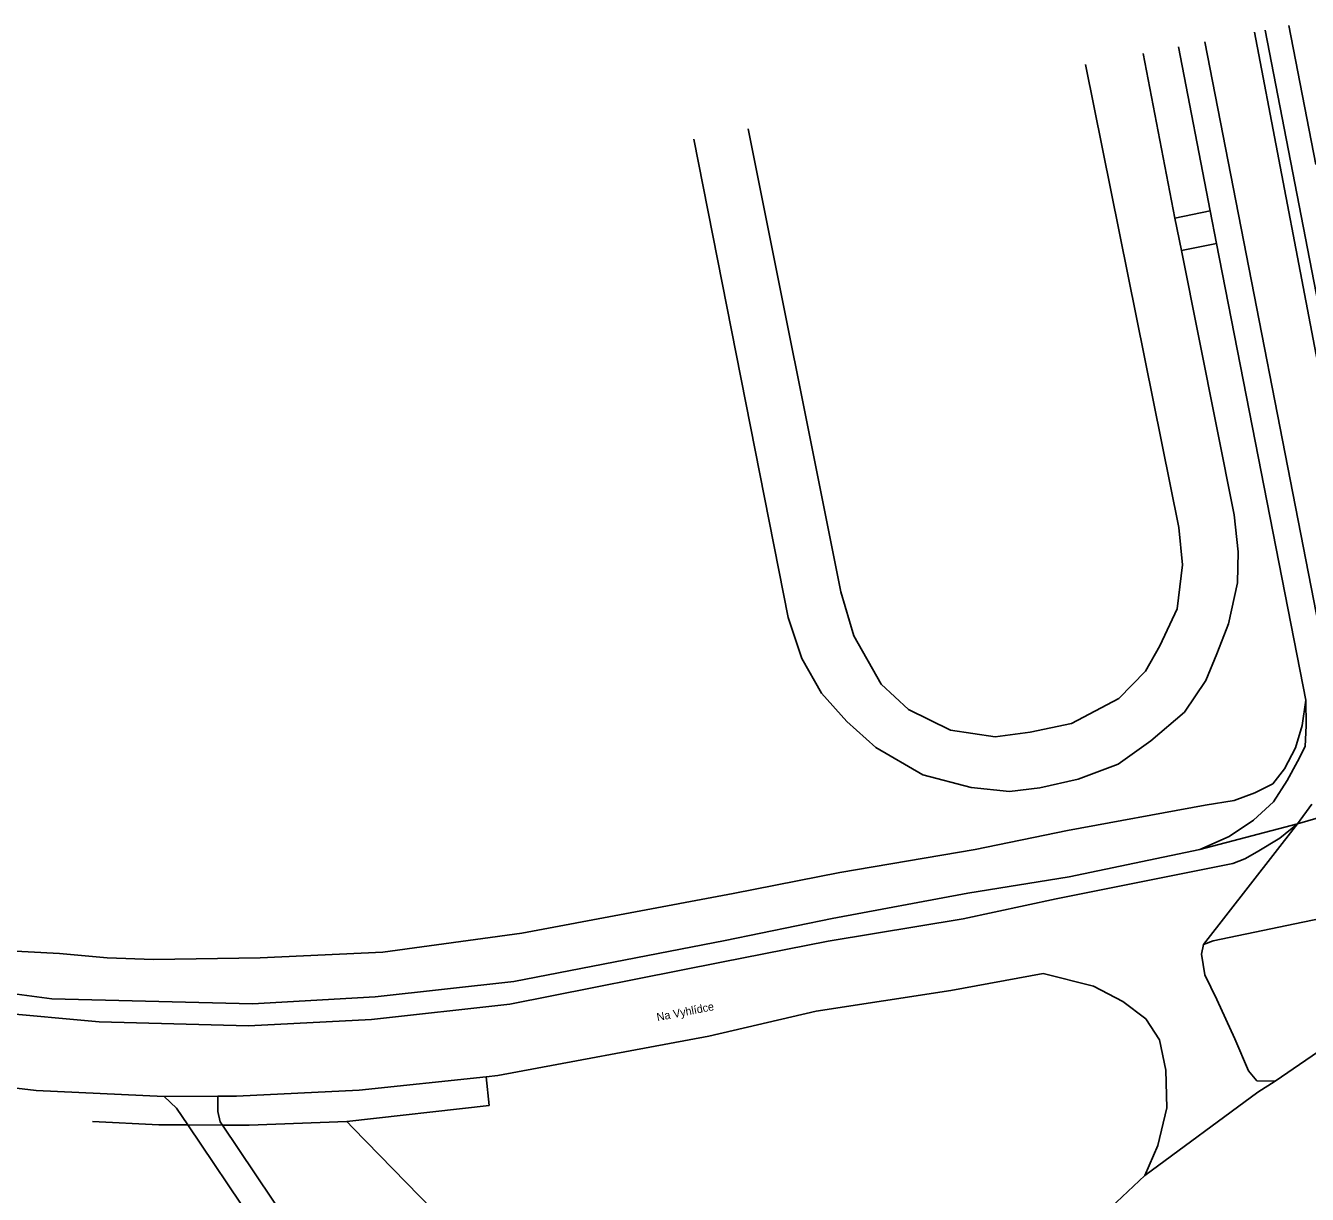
# Model space of a CAD drawing. Extents: x -452714 to -451134, y -1100194 to -1099694.
# Drawn here: x -452627.8 to -452516.4, y -1100019.1 to -1099917.5 of the extents above; entities that cross this region are included whole.
import ezdxf

# ---------------------------------------------------------------- set-up
doc = ezdxf.new("R2010")
doc.units = 0
doc.layers.add('Polohopis', color=7, linetype='Continuous')

msp = doc.modelspace()

# ---------------------------------------------------------------- linework, layer by layer
at = {"layer": 'Polohopis'}
for p, q in [((-452514.6, -1099951.28), (-452520.94, -1099918.08)), ((-452514.6, -1099951.28), (-452520.94, -1099918.08)), ((-452520.03, -1099917.9), (-452513.93, -1099949.28)), ((-452520.03, -1099917.9), (-452513.93, -1099949.28)), ((-452515.62, -1099929.58), (-452517.98, -1099917.51)), ((-452515.62, -1099929.58), (-452517.98, -1099917.51)), ((-452527.57, -1099919.35), (-452524.8, -1099933.61)), ((-452527.57, -1099919.35), (-452524.8, -1099933.61)), ((-452514.22, -1099975.53), (-452525.28, -1099918.91)), ((-452514.22, -1099975.53), (-452525.28, -1099918.91)), ((-452530.64, -1099919.93), (-452527.86, -1099934.24)), ((-452530.64, -1099919.93), (-452527.86, -1099934.24)), ((-452535.64, -1099920.89), (-452527.52, -1099961.12)), ((-452535.64, -1099920.89), (-452527.52, -1099961.12)), ((-452556.91, -1099966.72), (-452564.95, -1099926.49)), ((-452556.91, -1099966.72), (-452564.95, -1099926.49)), ((-452561.48, -1099968.96), (-452569.67, -1099927.39)), ((-452561.48, -1099968.96), (-452569.67, -1099927.39)), ((-452527.86, -1099934.24), (-452524.8, -1099933.61)), ((-452527.86, -1099934.24), (-452524.8, -1099933.61)), ((-452524.8, -1099933.61), (-452524.25, -1099936.46)), ((-452524.8, -1099933.61), (-452524.25, -1099936.46)), ((-452527.86, -1099934.24), (-452527.29, -1099937.07)), ((-452527.86, -1099934.24), (-452527.29, -1099937.07)), ((-452527.29, -1099937.07), (-452524.25, -1099936.46)), ((-452527.29, -1099937.07), (-452524.25, -1099936.46)), ((-452527.29, -1099937.07), (-452522.72, -1099960.03)), ((-452527.29, -1099937.07), (-452522.72, -1099960.03)), ((-452524.25, -1099936.46), (-452516.48, -1099976.13)), ((-452524.25, -1099936.46), (-452516.48, -1099976.13)), ((-452522.72, -1099960.03), (-452522.36, -1099963.26)), ((-452522.72, -1099960.03), (-452522.36, -1099963.26)), ((-452527.52, -1099961.12), (-452527.22, -1099964.38)), ((-452527.52, -1099961.12), (-452527.22, -1099964.38)), ((-452522.36, -1099963.26), (-452522.43, -1099965.95)), ((-452522.36, -1099963.26), (-452522.43, -1099965.95)), ((-452527.22, -1099964.38), (-452527.68, -1099968.19)), ((-452527.22, -1099964.38), (-452527.68, -1099968.19)), ((-452522.43, -1099965.95), (-452523.22, -1099969.5)), ((-452522.43, -1099965.95), (-452523.22, -1099969.5)), ((-452555.77, -1099970.55), (-452556.91, -1099966.72)), ((-452555.77, -1099970.55), (-452556.91, -1099966.72)), ((-452527.68, -1099968.19), (-452529.17, -1099971.41)), ((-452527.68, -1099968.19), (-452529.17, -1099971.41)), ((-452560.29, -1099972.52), (-452561.48, -1099968.96)), ((-452560.29, -1099972.52), (-452561.48, -1099968.96)), ((-452523.22, -1099969.5), (-452524.23, -1099972.12)), ((-452523.22, -1099969.5), (-452524.23, -1099972.12)), ((-452553.4, -1099974.75), (-452555.77, -1099970.55)), ((-452553.4, -1099974.75), (-452555.77, -1099970.55)), ((-452529.17, -1099971.41), (-452530.43, -1099973.63)), ((-452529.17, -1099971.41), (-452530.43, -1099973.63)), ((-452558.59, -1099975.54), (-452560.29, -1099972.52)), ((-452558.59, -1099975.54), (-452560.29, -1099972.52)), ((-452524.23, -1099972.12), (-452525.18, -1099974.42)), ((-452524.23, -1099972.12), (-452525.18, -1099974.42)), ((-452530.43, -1099973.63), (-452532.73, -1099976)), ((-452530.43, -1099973.63), (-452532.73, -1099976)), ((-452551.03, -1099976.96), (-452553.4, -1099974.75)), ((-452551.03, -1099976.96), (-452553.4, -1099974.75)), ((-452525.18, -1099974.42), (-452527.02, -1099977.18)), ((-452525.18, -1099974.42), (-452527.02, -1099977.18)), ((-452556.39, -1099977.98), (-452558.59, -1099975.54)), ((-452556.39, -1099977.98), (-452558.59, -1099975.54)), ((-452532.73, -1099976), (-452536.87, -1099978.16)), ((-452532.73, -1099976), (-452536.87, -1099978.16)), ((-452516.48, -1099976.13), (-452516.8, -1099978.34)), ((-452516.48, -1099976.13), (-452516.8, -1099978.34)), ((-452516.48, -1099976.13), (-452516.46, -1099978.34)), ((-452516.48, -1099976.13), (-452516.46, -1099978.34)), ((-452547.37, -1099978.75), (-452551.03, -1099976.96)), ((-452547.37, -1099978.75), (-452551.03, -1099976.96)), ((-452527.02, -1099977.18), (-452529.97, -1099979.67)), ((-452527.02, -1099977.18), (-452529.97, -1099979.67)), ((-452553.86, -1099980.26), (-452556.39, -1099977.98)), ((-452553.86, -1099980.26), (-452556.39, -1099977.98)), ((-452536.87, -1099978.16), (-452540.45, -1099978.92)), ((-452536.87, -1099978.16), (-452540.45, -1099978.92)), ((-452516.8, -1099978.34), (-452517.4, -1099980.27)), ((-452516.8, -1099978.34), (-452517.4, -1099980.27)), ((-452516.46, -1099978.34), (-452516.54, -1099980.16)), ((-452516.46, -1099978.34), (-452516.54, -1099980.16)), ((-452543.49, -1099979.34), (-452547.37, -1099978.75)), ((-452543.49, -1099979.34), (-452547.37, -1099978.75)), ((-452540.45, -1099978.92), (-452543.49, -1099979.34)), ((-452540.45, -1099978.92), (-452543.49, -1099979.34)), ((-452549.79, -1099982.62), (-452553.86, -1099980.26)), ((-452549.79, -1099982.62), (-452553.86, -1099980.26)), ((-452529.97, -1099979.67), (-452532.8, -1099981.7)), ((-452529.97, -1099979.67), (-452532.8, -1099981.7)), ((-452517.4, -1099980.27), (-452518.34, -1099982.11)), ((-452517.4, -1099980.27), (-452518.34, -1099982.11)), ((-452516.54, -1099980.16), (-452517.2, -1099981.47)), ((-452516.54, -1099980.16), (-452517.2, -1099981.47)), ((-452532.8, -1099981.7), (-452536.27, -1099983.02)), ((-452532.8, -1099981.7), (-452536.27, -1099983.02)), ((-452517.2, -1099981.47), (-452518.1, -1099983.11)), ((-452517.2, -1099981.47), (-452518.1, -1099983.11)), ((-452545.59, -1099983.74), (-452549.79, -1099982.62)), ((-452545.59, -1099983.74), (-452549.79, -1099982.62)), ((-452518.34, -1099982.11), (-452519.36, -1099983.42)), ((-452518.34, -1099982.11), (-452519.36, -1099983.42)), ((-452542.25, -1099984.07), (-452545.59, -1099983.74)), ((-452542.25, -1099984.07), (-452545.59, -1099983.74)), ((-452539.62, -1099983.75), (-452542.25, -1099984.07)), ((-452539.62, -1099983.75), (-452542.25, -1099984.07)), ((-452536.27, -1099983.02), (-452539.62, -1099983.75)), ((-452536.27, -1099983.02), (-452539.62, -1099983.75)), ((-452519.36, -1099983.42), (-452520.93, -1099984.2)), ((-452519.36, -1099983.42), (-452520.93, -1099984.2)), ((-452518.1, -1099983.11), (-452519.29, -1099984.99)), ((-452518.1, -1099983.11), (-452519.29, -1099984.99)), ((-452505.84, -1099983.57), (-452517.2, -1099986.88)), ((-452505.84, -1099983.57), (-452517.2, -1099986.88)), ((-452522.72, -1099984.85), (-452525.24, -1099985.26)), ((-452522.72, -1099984.85), (-452525.24, -1099985.26)), ((-452520.93, -1099984.2), (-452522.72, -1099984.85)), ((-452520.93, -1099984.2), (-452522.72, -1099984.85)), ((-452519.29, -1099984.99), (-452521.03, -1099986.58)), ((-452519.29, -1099984.99), (-452521.03, -1099986.58)), ((-452537.19, -1099987.48), (-452525.24, -1099985.26)), ((-452537.19, -1099987.48), (-452525.24, -1099985.26)), ((-452517.2, -1099986.88), (-452515.96, -1099985.19)), ((-452517.2, -1099986.88), (-452515.96, -1099985.19)), ((-452525.7, -1099989.12), (-452517.2, -1099986.88)), ((-452525.7, -1099989.12), (-452517.2, -1099986.88)), ((-452525.38, -1099997.38), (-452517.2, -1099986.88)), ((-452525.38, -1099997.38), (-452517.2, -1099986.88)), ((-452521.03, -1099986.58), (-452523.16, -1099987.98)), ((-452521.03, -1099986.58), (-452523.16, -1099987.98)), ((-452518.74, -1099988.12), (-452517.2, -1099986.88)), ((-452518.74, -1099988.12), (-452517.2, -1099986.88)), ((-452545.23, -1099989.12), (-452537.19, -1099987.48)), ((-452545.23, -1099989.12), (-452537.19, -1099987.48)), ((-452525.7, -1099989.12), (-452523.16, -1099987.98)), ((-452525.7, -1099989.12), (-452523.16, -1099987.98)), ((-452520.73, -1099989.32), (-452518.74, -1099988.12)), ((-452520.73, -1099989.32), (-452518.74, -1099988.12)), ((-452556.98, -1099991.13), (-452545.23, -1099989.12)), ((-452556.98, -1099991.13), (-452545.23, -1099989.12)), ((-452537.06, -1099991.49), (-452525.7, -1099989.12)), ((-452537.06, -1099991.49), (-452525.7, -1099989.12)), ((-452521.79, -1099989.92), (-452520.73, -1099989.32)), ((-452521.79, -1099989.92), (-452520.73, -1099989.32)), ((-452538.2, -1099993.4), (-452522.84, -1099990.35)), ((-452538.2, -1099993.4), (-452522.84, -1099990.35)), ((-452522.84, -1099990.35), (-452521.79, -1099989.92)), ((-452522.84, -1099990.35), (-452521.79, -1099989.92)), ((-452566.26, -1099992.94), (-452556.98, -1099991.13)), ((-452566.26, -1099992.94), (-452556.98, -1099991.13)), ((-452545.88, -1099992.92), (-452537.06, -1099991.49)), ((-452545.88, -1099992.92), (-452537.06, -1099991.49)), ((-452584.62, -1099996.39), (-452566.26, -1099992.94)), ((-452584.62, -1099996.39), (-452566.26, -1099992.94)), ((-452557.66, -1099995.12), (-452545.88, -1099992.92)), ((-452557.66, -1099995.12), (-452545.88, -1099992.92)), ((-452538.2, -1099993.4), (-452546.26, -1099995.14)), ((-452538.2, -1099993.4), (-452546.26, -1099995.14)), ((-452524.53, -1099997.05), (-452506.96, -1099993.4)), ((-452524.53, -1099997.05), (-452506.96, -1099993.4)), ((-452566.96, -1099997.03), (-452557.66, -1099995.12)), ((-452566.96, -1099997.03), (-452557.66, -1099995.12)), ((-452546.26, -1099995.14), (-452558, -1099997.08)), ((-452546.26, -1099995.14), (-452558, -1099997.08)), ((-452596.71, -1099998.03), (-452584.62, -1099996.39)), ((-452596.71, -1099998.03), (-452584.62, -1099996.39)), ((-452585.33, -1100000.58), (-452566.96, -1099997.03)), ((-452585.33, -1100000.58), (-452566.96, -1099997.03)), ((-452558, -1099997.08), (-452567.28, -1099998.91)), ((-452558, -1099997.08), (-452567.28, -1099998.91)), ((-452525.38, -1099997.38), (-452524.53, -1099997.05)), ((-452525.38, -1099997.38), (-452524.53, -1099997.05)), ((-452631.13, -1099997.83), (-452624.81, -1099998.16)), ((-452631.13, -1099997.83), (-452624.81, -1099998.16)), ((-452624.81, -1099998.16), (-452620.66, -1099998.53)), ((-452624.81, -1099998.16), (-452620.66, -1099998.53)), ((-452607.37, -1099998.54), (-452596.71, -1099998.03)), ((-452607.37, -1099998.54), (-452596.71, -1099998.03)), ((-452525.56, -1099998.21), (-452525.38, -1099997.38)), ((-452525.56, -1099998.21), (-452525.38, -1099997.38)), ((-452525.27, -1100000.01), (-452525.56, -1099998.21)), ((-452525.27, -1100000.01), (-452525.56, -1099998.21)), ((-452620.66, -1099998.53), (-452616.66, -1099998.68)), ((-452620.66, -1099998.53), (-452616.66, -1099998.68)), ((-452616.66, -1099998.68), (-452607.37, -1099998.54)), ((-452616.66, -1099998.68), (-452607.37, -1099998.54)), ((-452567.28, -1099998.91), (-452585.67, -1100002.57)), ((-452567.28, -1099998.91), (-452585.67, -1100002.57)), ((-452504.73, -1099999.32), (-452519.14, -1100009.24)), ((-452504.73, -1099999.32), (-452519.14, -1100009.24)), ((-452597.37, -1100001.92), (-452585.33, -1100000.58)), ((-452597.37, -1100001.92), (-452585.33, -1100000.58)), ((-452547.33, -1100001.38), (-452539.31, -1099999.9)), ((-452547.33, -1100001.38), (-452539.31, -1099999.9)), ((-452539.31, -1099999.9), (-452534.93, -1100001.01)), ((-452539.31, -1099999.9), (-452534.93, -1100001.01)), ((-452524.23, -1100002.15), (-452525.27, -1100000.01)), ((-452524.23, -1100002.15), (-452525.27, -1100000.01)), ((-452632.2, -1100001.21), (-452625.48, -1100002.11)), ((-452632.2, -1100001.21), (-452625.48, -1100002.11)), ((-452559.04, -1100003.18), (-452547.33, -1100001.38)), ((-452559.04, -1100003.18), (-452547.33, -1100001.38)), ((-452534.93, -1100001.01), (-452532.4, -1100002.32)), ((-452534.93, -1100001.01), (-452532.4, -1100002.32)), ((-452625.48, -1100002.11), (-452608.05, -1100002.53)), ((-452625.48, -1100002.11), (-452608.05, -1100002.53)), ((-452608.05, -1100002.53), (-452597.37, -1100001.92)), ((-452608.05, -1100002.53), (-452597.37, -1100001.92)), ((-452585.67, -1100002.57), (-452597.71, -1100003.89)), ((-452585.67, -1100002.57), (-452597.71, -1100003.89)), ((-452532.4, -1100002.32), (-452530.39, -1100003.83)), ((-452532.4, -1100002.32), (-452530.39, -1100003.83)), ((-452522.67, -1100005.58), (-452524.23, -1100002.15)), ((-452522.67, -1100005.58), (-452524.23, -1100002.15)), ((-452621.36, -1100004.1), (-452630.88, -1100003.24)), ((-452621.36, -1100004.1), (-452630.88, -1100003.24)), ((-452597.71, -1100003.89), (-452608.38, -1100004.45)), ((-452597.71, -1100003.89), (-452608.38, -1100004.45)), ((-452568.38, -1100005.33), (-452559.04, -1100003.18)), ((-452568.38, -1100005.33), (-452559.04, -1100003.18)), ((-452530.39, -1100003.83), (-452529.22, -1100005.65)), ((-452530.39, -1100003.83), (-452529.22, -1100005.65)), ((-452608.38, -1100004.45), (-452621.36, -1100004.1)), ((-452608.38, -1100004.45), (-452621.36, -1100004.1)), ((-452586.73, -1100008.76), (-452568.38, -1100005.33)), ((-452586.73, -1100008.76), (-452568.38, -1100005.33)), ((-452529.22, -1100005.65), (-452528.66, -1100008.3)), ((-452529.22, -1100005.65), (-452528.66, -1100008.3)), ((-452521.47, -1100008.37), (-452522.67, -1100005.58)), ((-452521.47, -1100008.37), (-452522.67, -1100005.58)), ((-452528.66, -1100008.3), (-452528.56, -1100011.58)), ((-452528.66, -1100008.3), (-452528.56, -1100011.58)), ((-452520.74, -1100009.22), (-452521.47, -1100008.37)), ((-452520.74, -1100009.22), (-452521.47, -1100008.37)), ((-452639.04, -1100008.6), (-452626.84, -1100010.06)), ((-452598.76, -1100010.03), (-452587.74, -1100008.87)), ((-452598.76, -1100010.03), (-452587.74, -1100008.87)), ((-452587.74, -1100008.87), (-452586.73, -1100008.76)), ((-452587.74, -1100008.87), (-452586.73, -1100008.76)), ((-452587.46, -1100011.37), (-452587.74, -1100008.87)), ((-452587.46, -1100011.37), (-452587.74, -1100008.87)), ((-452519.14, -1100009.24), (-452520.74, -1100009.22)), ((-452519.14, -1100009.24), (-452520.74, -1100009.22)), ((-452520.65, -1100010.21), (-452519.14, -1100009.24)), ((-452520.65, -1100010.21), (-452519.14, -1100009.24)), ((-452626.84, -1100010.06), (-452615.72, -1100010.59)), ((-452626.84, -1100010.06), (-452615.72, -1100010.59)), ((-452615.72, -1100010.59), (-452611.06, -1100010.57)), ((-452615.72, -1100010.59), (-452611.06, -1100010.57)), ((-452614.64, -1100011.59), (-452615.72, -1100010.59)), ((-452614.64, -1100011.59), (-452615.72, -1100010.59)), ((-452611.05, -1100011.88), (-452611.06, -1100010.57)), ((-452611.06, -1100010.57), (-452609.43, -1100010.57)), ((-452611.05, -1100011.88), (-452611.06, -1100010.57)), ((-452611.06, -1100010.57), (-452609.43, -1100010.57)), ((-452609.43, -1100010.57), (-452598.76, -1100010.03)), ((-452609.43, -1100010.57), (-452598.76, -1100010.03)), ((-452530.48, -1100017.45), (-452520.65, -1100010.21)), ((-452530.48, -1100017.45), (-452520.65, -1100010.21)), ((-452613.65, -1100013.06), (-452614.64, -1100011.59)), ((-452613.65, -1100013.06), (-452614.64, -1100011.59)), ((-452599.83, -1100012.76), (-452587.46, -1100011.37)), ((-452599.83, -1100012.76), (-452587.46, -1100011.37)), ((-452528.56, -1100011.58), (-452529.35, -1100014.84)), ((-452528.56, -1100011.58), (-452529.35, -1100014.84)), ((-452621.96, -1100012.77), (-452616.19, -1100013.05)), ((-452621.96, -1100012.77), (-452616.19, -1100013.05)), ((-452610.86, -1100012.78), (-452611.05, -1100011.88)), ((-452610.86, -1100012.78), (-452611.05, -1100011.88)), ((-452610.66, -1100013.08), (-452610.86, -1100012.78)), ((-452610.66, -1100013.08), (-452610.86, -1100012.78)), ((-452608.33, -1100013.09), (-452599.83, -1100012.76)), ((-452608.33, -1100013.09), (-452599.83, -1100012.76)), ((-452599.83, -1100012.76), (-452599.32, -1100013.3)), ((-452599.83, -1100012.76), (-452599.32, -1100013.3)), ((-452616.19, -1100013.05), (-452613.65, -1100013.06)), ((-452616.19, -1100013.05), (-452613.65, -1100013.06)), ((-452606.18, -1100024.18), (-452613.65, -1100013.06)), ((-452613.65, -1100013.06), (-452610.66, -1100013.08)), ((-452606.18, -1100024.18), (-452613.65, -1100013.06)), ((-452613.65, -1100013.06), (-452610.66, -1100013.08)), ((-452610.66, -1100013.08), (-452608.33, -1100013.09)), ((-452610.66, -1100013.08), (-452604.1, -1100022.83)), ((-452610.66, -1100013.08), (-452608.33, -1100013.09)), ((-452610.66, -1100013.08), (-452604.1, -1100022.83)), ((-452599.32, -1100013.3), (-452578.38, -1100034.77)), ((-452599.32, -1100013.3), (-452578.38, -1100034.77)), ((-452529.35, -1100014.84), (-452530.48, -1100017.45)), ((-452529.35, -1100014.84), (-452530.48, -1100017.45)), ((-452535.84, -1100022.47), (-452530.48, -1100017.45)), ((-452535.84, -1100022.47), (-452530.48, -1100017.45))]:
    msp.add_line(p, q, dxfattribs=at)

# ---------------------------------------------------------------- texts
msp.add_text('Na Vyhlídce', height=0.7, rotation=11, dxfattribs=at).set_placement((-452572.84, -1100004.04))
msp.add_text('Na Vyhlídce', height=0.7, rotation=11, dxfattribs=at).set_placement((-452572.84, -1100004.04))

doc.saveas('drawing.dxf')
